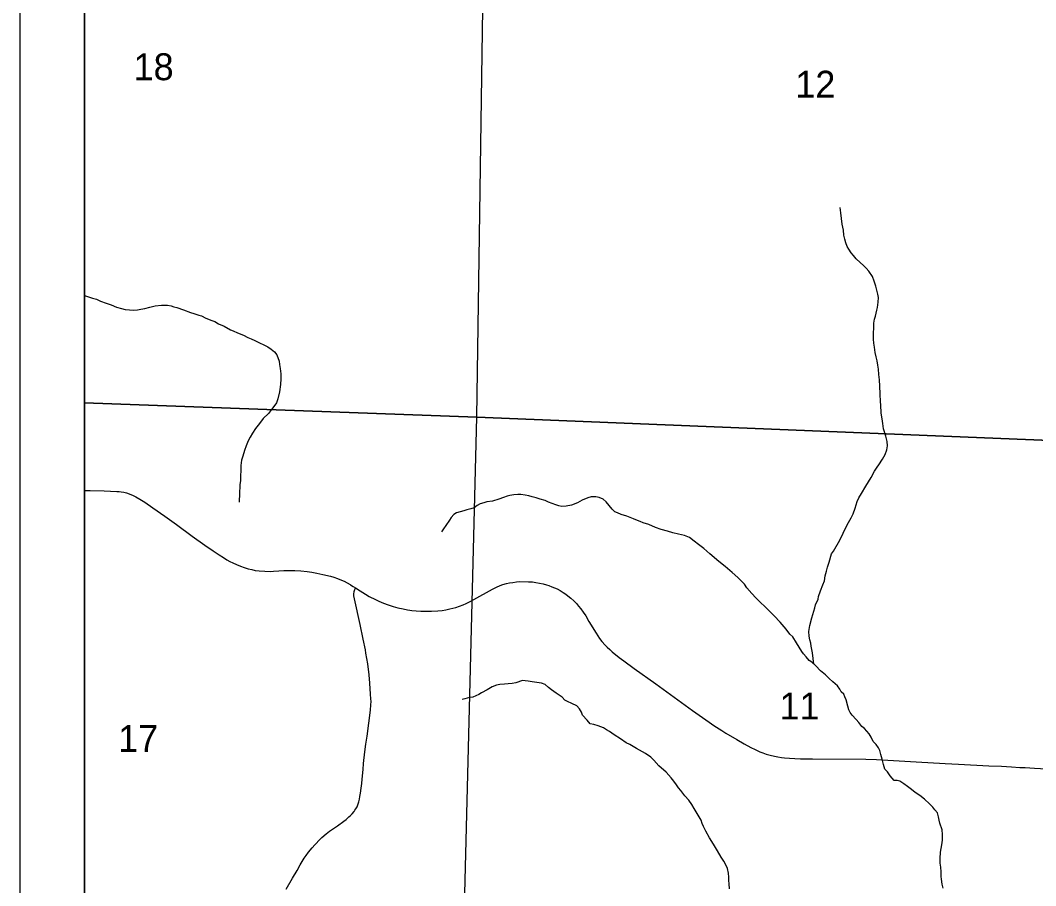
# Model space of a CAD drawing. Extents: x 0 to 34, y 0 to 22.
# Drawn here: x 2.5 to 4.079, y 17.981 to 19.327 of the extents above; entities that cross this region are included whole.
import ezdxf

# ---------------------------------------------------------------- set-up
doc = ezdxf.new("R2010")
doc.units = 0
for name, color, linetype in [('GM_X_Corporation', 7, 'Continuous'), ('GM_X_County_Road', 7, 'Continuous'), ('GM_X_Minor_River', 7, 'Continuous'), ('GM_X_Section_Text', 7, 'Continuous'), ('GM_X_State_Route', 7, 'Continuous'), ('SH_Data', 7, 'Continuous')]:
    doc.layers.add(name, color=color, linetype=linetype)

msp = doc.modelspace()

# ---------------------------------------------------------------- linework, layer by layer
at = {"layer": 'GM_X_Corporation'}
for points in [[(9.4, 16.4853), (9.4, 20.4), (2.6, 20.4), (2.6, 16.6918), (3.1555, 16.6686), (3.1684, 16.6682), (4.0515, 16.6368), (4.1011, 16.6362), (4.1867, 16.6352), (4.5473, 16.6256), (4.6351, 16.6229), (5.4202, 16.5982), (6.0834, 16.5816), (6.2194, 16.578), (8.0963, 16.5226), (9.09, 16.4927)], [(6.2895, 20.4), (2.6, 20.4), (2.6, 16.6918), (3.1555, 16.6686), (3.1684, 16.6682), (4.0515, 16.6368), (4.1011, 16.6362), (4.1867, 16.6352), (4.5473, 16.6256), (4.6351, 16.6229), (5.4202, 16.5982), (6.0834, 16.5816), (6.2194, 16.578), (6.2729, 18.2077), (6.2744, 18.4654), (6.2786, 18.5898), (6.292, 18.5898), (6.2926, 19.1539), (6.2942, 19.6131), (6.2595, 19.6124)], [(2.6, 19.8164), (2.6, 18.7322), (3.2101, 18.7098), (3.226, 19.805)], [(3.2518, 19.8039), (4.2724, 19.7849), (4.2417, 18.6679), (3.2101, 18.7098), (3.226, 19.805)], [(2.6, 18.7322), (2.6, 17.7192), (3.1848, 17.7013), (3.2101, 18.7098)], [(4.2417, 18.6679), (4.2074, 17.6513), (3.1848, 17.7013), (3.2101, 18.7098)]]:
    msp.add_lwpolyline(points, close=True, dxfattribs=at)
at = {"layer": 'GM_X_County_Road'}
for points in [[(3.0212, 18.4445), (3.0287, 18.4397), (3.0368, 18.4345), (3.0428, 18.431), (3.0523, 18.4261), (3.0575, 18.4237), (3.0647, 18.4206), (3.072, 18.4179), (3.0799, 18.4154), (3.087, 18.4135), (3.0956, 18.4115), (3.1024, 18.4101), (3.1059, 18.4097), (3.1092, 18.4093), (3.1158, 18.4086), (3.1231, 18.4081), (3.1332, 18.4079), (3.1394, 18.408), (3.1496, 18.4086), (3.156, 18.4093), (3.162, 18.4103), (3.1678, 18.4115), (3.1728, 18.4126), (3.1775, 18.414), (3.1833, 18.4159), (3.1886, 18.4179), (3.1935, 18.4201), (3.1984, 18.4225), (3.2054, 18.4262), (3.2342, 18.4422), (3.2405, 18.4455), (3.2461, 18.4478), (3.2506, 18.4495), (3.2561, 18.451), (3.2608, 18.452), (3.2659, 18.4529), (3.2718, 18.4537), (3.2769, 18.454), (3.2906, 18.4539), (3.2965, 18.4535), (3.3019, 18.4528), (3.3075, 18.4517), (3.3132, 18.4504), (3.3183, 18.449), (3.3222, 18.4478), (3.3267, 18.4462), (3.3311, 18.4444), (3.3351, 18.4426), (3.3398, 18.4401), (3.3443, 18.4374), (3.3486, 18.4346), (3.3518, 18.4321), (3.3562, 18.4285), (3.3608, 18.4242), (3.3649, 18.42), (3.3683, 18.4161), (3.3718, 18.4116), (3.3754, 18.4066), (3.3794, 18.4007), (3.3845, 18.3922), (3.3954, 18.3741), (3.3983, 18.3695), (3.401, 18.3656), (3.4047, 18.3608), (3.4095, 18.3554), (3.413, 18.352), (3.4168, 18.3484), (3.4208, 18.3447), (3.4313, 18.3362), (3.4387, 18.3306), (3.4548, 18.319), (3.4882, 18.2952), (3.4999, 18.2867), (3.5455, 18.2537), (3.5712, 18.2354), (3.5787, 18.2302), (3.5909, 18.2223), (3.5973, 18.2184), (3.6145, 18.2082), (3.6256, 18.2019), (3.6363, 18.1961), (3.6427, 18.1928), (3.6502, 18.1894), (3.6548, 18.1876), (3.6602, 18.1857), (3.6663, 18.184), (3.6732, 18.1825), (3.6782, 18.1815), (3.6837, 18.1806), (3.6887, 18.18), (3.6963, 18.1792), (3.7046, 18.1787), (3.7136, 18.1784), (3.7321, 18.1782), (3.8152, 18.178), (3.8315, 18.1772), (3.8933, 18.1736), (3.9385, 18.171), (3.9593, 18.1699), (4.0064, 18.1677), (4.0262, 18.1667), (4.0417, 18.1658), (4.0546, 18.1651), (4.0627, 18.1647), (4.0773, 18.1639), (4.1047, 18.1625)], [(2.9133, 17.9756), (2.9234, 17.9925), (2.9306, 18.0048), (2.9351, 18.0132), (2.9414, 18.0236), (2.9447, 18.0281), (2.9483, 18.0331), (2.954, 18.04), (2.9582, 18.0447), (2.9662, 18.0532), (2.9688, 18.0558), (2.9756, 18.0617), (2.981, 18.0658), (2.9887, 18.0711), (2.9934, 18.0742), (3.003, 18.0812), (3.0066, 18.084), (3.0111, 18.0879), (3.0133, 18.0899), (3.016, 18.0927), (3.0191, 18.0962), (3.0204, 18.0983), (3.022, 18.1008), (3.0237, 18.1038), (3.0249, 18.1069), (3.0264, 18.1114), (3.0275, 18.1157), (3.0283, 18.1198), (3.029, 18.1248), (3.0302, 18.1328), (3.031, 18.1398), (3.0317, 18.1469), (3.0331, 18.1617), (3.0338, 18.1709), (3.036, 18.1891), (3.0376, 18.2011), (3.0394, 18.2138), (3.0447, 18.2542), (3.0454, 18.2624), (3.0455, 18.2677), (3.0453, 18.2718), (3.0448, 18.2791), (3.0438, 18.2963), (3.0425, 18.3092), (3.0403, 18.326), (3.0375, 18.3428), (3.0367, 18.3479), (3.0335, 18.3643), (3.0288, 18.3876), (3.0197, 18.4271), (3.019, 18.4318), (3.0188, 18.4344), (3.0191, 18.4387), (3.0197, 18.4404), (3.0212, 18.4445)]]:
    msp.add_lwpolyline(points, dxfattribs=at)
at = {"layer": 'GM_X_Minor_River'}
for points in [[(3.7342, 18.3258), (3.7323, 18.3431), (3.7299, 18.3536), (3.7295, 18.3582), (3.7279, 18.3634), (3.7267, 18.3694), (3.7262, 18.3765), (3.728, 18.3859), (3.7313, 18.3976), (3.736, 18.4135), (3.7367, 18.418), (3.7411, 18.4267), (3.7415, 18.4308), (3.7448, 18.4395), (3.7481, 18.4493), (3.7506, 18.4554), (3.7517, 18.4629), (3.7539, 18.4701), (3.7553, 18.4768), (3.7579, 18.4844), (3.7619, 18.4972), (3.7649, 18.5014), (3.7745, 18.5188), (3.78, 18.5294), (3.7859, 18.5422), (3.7922, 18.5532), (3.7952, 18.5593), (3.7985, 18.5683), (3.8018, 18.5789), (3.8044, 18.5842), (3.8084, 18.591), (3.8151, 18.6024), (3.8233, 18.616), (3.8288, 18.6258), (3.8326, 18.6319), (3.8352, 18.636), (3.8411, 18.6448), (3.8452, 18.652), (3.8478, 18.6591), (3.8488, 18.6655), (3.8484, 18.6723), (3.8464, 18.6806), (3.8428, 18.6918), (3.8416, 18.7001), (3.8404, 18.7072), (3.8387, 18.7162), (3.8382, 18.729), (3.8378, 18.7336), (3.8373, 18.7463), (3.8367, 18.758), (3.8362, 18.7678), (3.8354, 18.7761), (3.8349, 18.7844), (3.8337, 18.7907), (3.8325, 18.7975), (3.8313, 18.8039), (3.8297, 18.8107), (3.8285, 18.8186), (3.8276, 18.825), (3.8272, 18.8314), (3.8271, 18.8404), (3.8273, 18.8491), (3.8276, 18.8562), (3.8287, 18.8626), (3.8301, 18.8672), (3.8309, 18.8717), (3.8323, 18.8766), (3.8334, 18.8808), (3.8344, 18.8887), (3.8347, 18.8959), (3.8339, 18.9015), (3.8327, 18.9056), (3.8307, 18.9135), (3.828, 18.9214), (3.8256, 18.9286), (3.8195, 18.9372), (3.8156, 18.9417), (3.8114, 18.9461), (3.8065, 18.9506), (3.8003, 18.9562), (3.7957, 18.9614), (3.7923, 18.9655), (3.7888, 18.9712), (3.7861, 18.9757), (3.7841, 18.9813), (3.7826, 18.9869), (3.781, 18.9933), (3.7801, 19.0009), (3.7785, 19.0103), (3.7773, 19.0189), (3.7764, 19.0276), (3.7752, 19.0363)], [(2.6, 18.8991), (2.6027, 18.8981), (2.6076, 18.8967), (2.6122, 18.8952), (2.6183, 18.8934), (2.6247, 18.8904), (2.6335, 18.8875), (2.6411, 18.8846), (2.6498, 18.8813), (2.6574, 18.8791), (2.6631, 18.8776), (2.6699, 18.877), (2.676, 18.8766), (2.6824, 18.8767), (2.6877, 18.8779), (2.6938, 18.8791), (2.7017, 18.8811), (2.71, 18.883), (2.7194, 18.8843), (2.7289, 18.884), (2.7346, 18.8833), (2.7388, 18.8814), (2.7433, 18.8804), (2.754, 18.8771), (2.7646, 18.8727), (2.7699, 18.8712), (2.7775, 18.8686), (2.7817, 18.8676), (2.7886, 18.8642), (2.7977, 18.8602), (2.8023, 18.8587), (2.8083, 18.8554), (2.8171, 18.8513), (2.827, 18.8458), (2.8312, 18.8443), (2.8377, 18.841), (2.8472, 18.8373), (2.854, 18.834), (2.8593, 18.8318), (2.8647, 18.8292), (2.8708, 18.8259), (2.8799, 18.8222), (2.8852, 18.8196), (2.8902, 18.8159), (2.8955, 18.8114), (2.899, 18.8069), (2.9025, 18.7968), (2.903, 18.7919), (2.9042, 18.7859), (2.905, 18.7776), (2.9051, 18.7697), (2.9048, 18.761), (2.9031, 18.7493), (2.9006, 18.7384), (2.8984, 18.7323), (2.8943, 18.7266), (2.8909, 18.722), (2.8861, 18.7156), (2.8775, 18.708), (2.8719, 18.7), (2.8659, 18.6924), (2.8611, 18.6848), (2.8574, 18.6787), (2.8544, 18.6731), (2.8511, 18.6655), (2.8485, 18.6579), (2.846, 18.6492), (2.8442, 18.6428), (2.8431, 18.6349), (2.8428, 18.6266), (2.8425, 18.6194), (2.8423, 18.6115), (2.8416, 18.6047), (2.8412, 18.6006), (2.8409, 18.5945), (2.8407, 18.587), (2.8403, 18.5825), (2.8404, 18.5776)], [(3.3827, 18.5842), (3.374, 18.581), (3.3665, 18.5768), (3.3575, 18.573), (3.3488, 18.5714), (3.3424, 18.5709), (3.3378, 18.572), (3.3329, 18.5735), (3.3272, 18.5757), (3.3215, 18.5775), (3.3165, 18.5801), (3.3085, 18.5826), (3.3021, 18.5844), (3.296, 18.5862), (3.2911, 18.5873), (3.285, 18.5887), (3.2786, 18.5894), (3.2736, 18.5898), (3.2676, 18.5893), (3.2615, 18.5881), (3.2574, 18.5869), (3.2517, 18.585), (3.2442, 18.5823), (3.2344, 18.5795), (3.2257, 18.578), (3.2208, 18.5768), (3.2151, 18.5752), (3.2106, 18.5725), (3.2061, 18.5691), (3.2008, 18.5671), (3.1944, 18.5656), (3.1899, 18.5644), (3.1786, 18.5613), (3.1745, 18.5586), (3.17, 18.554), (3.1674, 18.5495), (3.1618, 18.5415), (3.1584, 18.5362), (3.1551, 18.5313)], [(3.9344, 18.0606), (3.9336, 18.0681), (3.93, 18.0782), (3.9292, 18.0827), (3.928, 18.088), (3.9264, 18.0943), (3.9226, 18.0988), (3.9191, 18.1033), (3.9142, 18.1081), (3.9061, 18.1155), (3.8989, 18.1211), (3.892, 18.1259), (3.8859, 18.1307), (3.8801, 18.1355), (3.8744, 18.1396), (3.8679, 18.1436), (3.8638, 18.1447), (3.8592, 18.1447), (3.8527, 18.1517), (3.8488, 18.1581), (3.8446, 18.1622), (3.8426, 18.1697), (3.8406, 18.1779), (3.8383, 18.185), (3.8367, 18.1914), (3.8348, 18.1955), (3.8309, 18.2007), (3.8263, 18.2055), (3.8232, 18.2123), (3.8201, 18.2171), (3.8132, 18.2253), (3.809, 18.2286), (3.8044, 18.235), (3.7998, 18.2394), (3.7936, 18.2461), (3.7906, 18.2506), (3.7886, 18.2547), (3.787, 18.2603), (3.7843, 18.2704), (3.7823, 18.2746), (3.7811, 18.2791), (3.7766, 18.2824), (3.7746, 18.2865), (3.7708, 18.2917), (3.7639, 18.298), (3.7581, 18.3032), (3.7524, 18.3092), (3.7447, 18.3155), (3.7375, 18.3229), (3.7313, 18.3285), (3.7271, 18.3311), (3.7222, 18.337), (3.7183, 18.3415), (3.7156, 18.3456), (3.7114, 18.3523), (3.7075, 18.359), (3.7017, 18.368), (3.6971, 18.3721), (3.691, 18.3799), (3.6818, 18.3911), (3.6726, 18.4007), (3.666, 18.4074), (3.658, 18.4156), (3.6515, 18.4216), (3.6442, 18.4286), (3.6377, 18.4357), (3.63, 18.4443), (3.6265, 18.4499), (3.6219, 18.4547), (3.6158, 18.4603), (3.6074, 18.4681), (3.5963, 18.4777), (3.5864, 18.4855), (3.5726, 18.4974), (3.5631, 18.5056), (3.555, 18.5119), (3.5482, 18.5171), (3.5409, 18.5226), (3.5333, 18.5256), (3.5238, 18.5281), (3.5147, 18.5299), (3.5067, 18.5324), (3.4968, 18.5353), (3.4877, 18.5382), (3.4778, 18.5427), (3.4687, 18.5456), (3.4641, 18.5474), (3.46, 18.5492), (3.4539, 18.5518), (3.4432, 18.5558), (3.4345, 18.5587), (3.4288, 18.5609), (3.4246, 18.5628), (3.4208, 18.5669), (3.4161, 18.5725), (3.4112, 18.5784), (3.4066, 18.5825), (3.4001, 18.5851), (3.3952, 18.5862), (3.388, 18.5861), (3.3827, 18.5842)], [(3.373, 18.2511), (3.3696, 18.256), (3.3657, 18.2608), (3.3577, 18.2645), (3.3513, 18.2674), (3.3471, 18.2697), (3.3429, 18.2741), (3.3333, 18.2804), (3.3261, 18.2856), (3.3215, 18.2893), (3.3165, 18.2941), (3.3108, 18.2963), (3.3036, 18.297), (3.296, 18.298), (3.29, 18.2991), (3.285, 18.2998), (3.2809, 18.3001), (3.2707, 18.2966), (3.265, 18.2954), (3.259, 18.295), (3.2533, 18.2946), (3.2457, 18.2941), (3.2404, 18.2929), (3.234, 18.2902), (3.2261, 18.2856), (3.2175, 18.281), (3.2134, 18.2787), (3.2085, 18.2764), (3.2036, 18.2744), (3.1987, 18.2736), (3.1915, 18.2717), (3.187, 18.2709)], [(3.6031, 17.9763), (3.6026, 17.9838), (3.6022, 17.9891), (3.6021, 17.994), (3.6016, 18.0007), (3.5997, 18.0078), (3.5977, 18.0123), (3.5942, 18.0194), (3.59, 18.0254), (3.5842, 18.0351), (3.5784, 18.0456), (3.5718, 18.0557), (3.566, 18.0657), (3.5625, 18.0732), (3.5606, 18.0777), (3.559, 18.0829), (3.5482, 18.1012), (3.5447, 18.1072), (3.5397, 18.1143), (3.5336, 18.121), (3.5274, 18.1292), (3.5236, 18.1333), (3.5205, 18.1381), (3.5163, 18.1434), (3.5124, 18.149), (3.5044, 18.1575), (3.4933, 18.1675), (3.4856, 18.1765), (3.4806, 18.1809), (3.4722, 18.1868), (3.4585, 18.1942), (3.4478, 18.2005), (3.4421, 18.2034), (3.4337, 18.2097), (3.4238, 18.2156), (3.4162, 18.2208), (3.4116, 18.2234), (3.407, 18.2267), (3.3987, 18.2296), (3.3918, 18.2318), (3.3865, 18.2329), (3.3815, 18.2385), (3.3746, 18.2463), (3.373, 18.2511)], [(3.9354, 17.9772), (3.9338, 17.9836), (3.933, 17.9911), (3.9322, 17.9952), (3.9325, 18.0027), (3.9316, 18.0099), (3.9308, 18.0162), (3.9307, 18.0234), (3.9313, 18.0331), (3.9331, 18.0444), (3.9345, 18.052), (3.9344, 18.0606)]]:
    msp.add_lwpolyline(points, dxfattribs=at)
at = {"layer": 'GM_X_State_Route'}
for points in [[(2.6, 18.5959), (2.6086, 18.5957), (2.6304, 18.5951), (2.6502, 18.5945), (2.6536, 18.5943), (2.6571, 18.5938), (2.6609, 18.5931), (2.6652, 18.592), (2.6691, 18.5907), (2.6754, 18.5883), (2.6798, 18.5862), (2.6861, 18.5826), (2.6937, 18.5778), (2.7063, 18.569), (2.7246, 18.5559), (2.7427, 18.5431), (2.7673, 18.525), (2.7872, 18.5108), (2.7998, 18.5021), (2.8092, 18.4957), (2.8158, 18.4916), (2.8214, 18.488), (2.8259, 18.4855), (2.8303, 18.4834), (2.8362, 18.4807), (2.8423, 18.4783), (2.8484, 18.476), (2.8546, 18.4742), (2.8602, 18.4728), (2.8655, 18.4716), (2.8717, 18.4706), (2.8803, 18.4702), (2.8886, 18.47), (2.8938, 18.4701), (2.902, 18.4707), (2.91, 18.4712), (2.9193, 18.4716), (2.9269, 18.4715), (2.9363, 18.4709), (2.9462, 18.4698), (2.9534, 18.4687), (2.9611, 18.4672), (2.9707, 18.4652), (2.9823, 18.4623), (2.9877, 18.4608), (2.9936, 18.4588), (2.9969, 18.4576), (3.0035, 18.4547), (3.0086, 18.4521), (3.0129, 18.4497)], [(3.0129, 18.4497), (3.0137, 18.4492), (3.0177, 18.4467), (3.0212, 18.4445)], [(3.0212, 18.4445), (3.0287, 18.4397), (3.0368, 18.4345), (3.0428, 18.431), (3.0523, 18.4261), (3.0575, 18.4237), (3.0647, 18.4206), (3.072, 18.4179), (3.0799, 18.4154), (3.087, 18.4135), (3.0956, 18.4115), (3.1024, 18.4101), (3.1059, 18.4097), (3.1092, 18.4093), (3.1158, 18.4086), (3.1231, 18.4081), (3.1332, 18.4079), (3.1394, 18.408), (3.1496, 18.4086), (3.156, 18.4093), (3.162, 18.4103), (3.1678, 18.4115), (3.1728, 18.4126), (3.1775, 18.414), (3.1833, 18.4159), (3.1886, 18.4179), (3.1935, 18.4201), (3.1984, 18.4225), (3.2054, 18.4262), (3.2342, 18.4422), (3.2405, 18.4455), (3.2461, 18.4478), (3.2506, 18.4495), (3.2561, 18.451), (3.2608, 18.452), (3.2659, 18.4529), (3.2718, 18.4537), (3.2769, 18.454), (3.2906, 18.4539), (3.2965, 18.4535), (3.3019, 18.4528), (3.3075, 18.4517), (3.3132, 18.4504), (3.3183, 18.449), (3.3222, 18.4478), (3.3267, 18.4462), (3.3311, 18.4444), (3.3351, 18.4426), (3.3398, 18.4401), (3.3443, 18.4374), (3.3486, 18.4346), (3.3518, 18.4321), (3.3562, 18.4285), (3.3608, 18.4242), (3.3649, 18.42), (3.3683, 18.4161), (3.3718, 18.4116), (3.3754, 18.4066), (3.3794, 18.4007), (3.3845, 18.3922), (3.3954, 18.3741), (3.3983, 18.3695), (3.401, 18.3656), (3.4047, 18.3608), (3.4095, 18.3554), (3.413, 18.352), (3.4168, 18.3484), (3.4208, 18.3447), (3.4313, 18.3362), (3.4387, 18.3306), (3.4548, 18.319), (3.4882, 18.2952), (3.4999, 18.2867), (3.5455, 18.2537), (3.5712, 18.2354), (3.5787, 18.2302), (3.5909, 18.2223), (3.5973, 18.2184), (3.6145, 18.2082), (3.6256, 18.2019), (3.6363, 18.1961), (3.6427, 18.1928), (3.6502, 18.1894), (3.6548, 18.1876), (3.6602, 18.1857), (3.6663, 18.184), (3.6732, 18.1825), (3.6782, 18.1815), (3.6837, 18.1806), (3.6887, 18.18), (3.6963, 18.1792), (3.7046, 18.1787), (3.7136, 18.1784), (3.7321, 18.1782), (3.8152, 18.178), (3.8315, 18.1772), (3.8933, 18.1736), (3.9385, 18.171), (3.9593, 18.1699), (4.0064, 18.1677), (4.0262, 18.1667), (4.0417, 18.1658), (4.0546, 18.1651), (4.0627, 18.1647), (4.0773, 18.1639), (4.1047, 18.1625)]]:
    msp.add_lwpolyline(points, dxfattribs=at)
at = {"layer": 'SH_Data'}
for points in [[(2.5, 20.5), (9.5, 20.5), (9.5, 13.5), (2.5, 13.5)], [(2.6, 20.4), (9.4, 20.4), (9.4, 13.6), (2.6, 13.6)]]:
    msp.add_lwpolyline(points, close=True, dxfattribs=at)

# ---------------------------------------------------------------- texts
at = {"layer": 'GM_X_Section_Text'}
for s, p in [('18', (2.6762, 19.2342)), ('12', (3.7054, 19.207)), ('11', (3.6808, 18.2396)), ('17', (2.6521, 18.1889))]:
    msp.add_text(s, height=0.04186, rotation=0, dxfattribs=at).set_placement(p)

doc.saveas('drawing.dxf')
